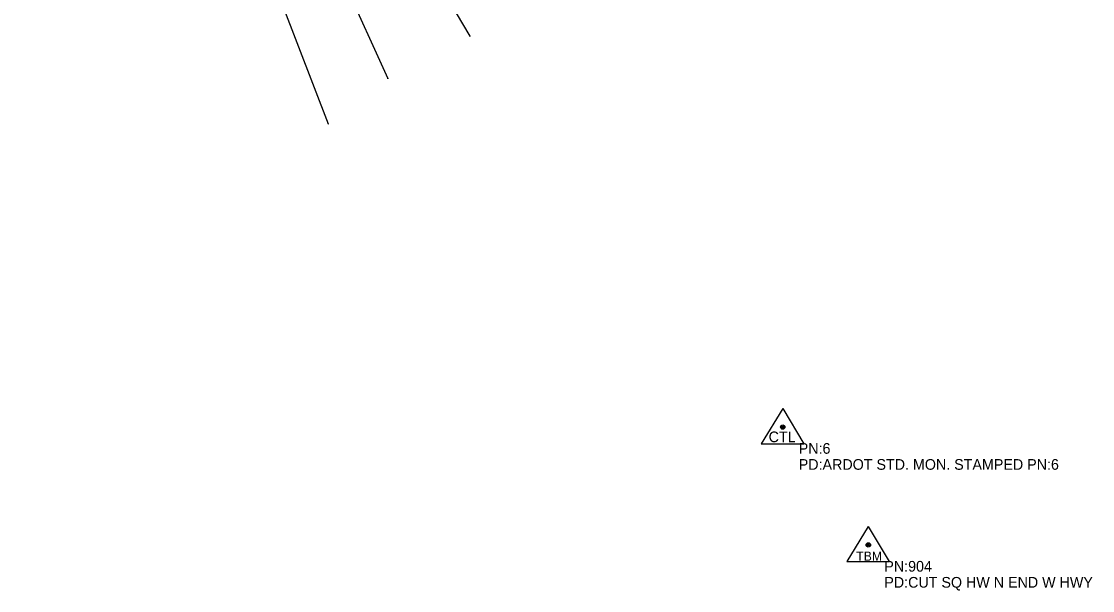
# Model space of a CAD drawing. Extents: x -99999 to 591807, y -99999 to 347168.
# Drawn here: x 589052 to 589554, y 343401 to 343667 of the extents above; entities that cross this region are included whole.
import ezdxf

# ---------------------------------------------------------------- set-up
doc = ezdxf.new("R2010")
doc.units = 0
for name, color, linetype in [('S_BREAKLINE', 7, 'Continuous'), ('S_GRD_PT_SYM', 7, 'Continuous'), ('S_PRIMARY_CTL', 7, 'Continuous'), ('S_PRIMARY_CTL_ANNOT', 7, 'Continuous')]:
    doc.layers.add(name, color=color, linetype=linetype)

msp = doc.modelspace()

# ---------------------------------------------------------------- linework, layer by layer
at = {"layer": 'S_BREAKLINE'}
for points in [[(589122.45, 343935.59), (589160.09, 343872.72), (589193.87, 343801.51), (589218.18, 343753.31), (589237.08, 343702.89), (589262.29, 343660.54)], [(589089.66, 343924.69), (589132.38, 343857.64), (589158.55, 343788.24), (589184.84, 343739), (589203.3, 343685.76), (589223.79, 343640.59)], [(589052.22, 343921.64), (589101.97, 343846.15), (589127.03, 343776.07), (589154.37, 343721.96), (589174.68, 343674.57), (589195.94, 343619.47)]]:
    msp.add_lwpolyline(points, dxfattribs=at)
at = {"layer": 'S_GRD_PT_SYM'}
for points in [[(589262.29, 343660.54), (589262.33, 343660.57), (589262.29, 343660.54), (589262.26, 343660.58), (589262.29, 343660.54), (589262.24, 343660.52), (589262.29, 343660.54), (589262.31, 343660.5)], [(589223.79, 343640.59), (589223.83, 343640.61), (589223.79, 343640.59), (589223.76, 343640.64), (589223.79, 343640.59), (589223.74, 343640.57), (589223.79, 343640.59), (589223.81, 343640.55)], [(589195.94, 343619.47), (589195.99, 343619.49), (589195.94, 343619.47), (589195.92, 343619.52), (589195.94, 343619.47), (589195.9, 343619.46), (589195.94, 343619.47), (589195.96, 343619.43)]]:
    msp.add_lwpolyline(points, close=True, dxfattribs=at)
at = {"layer": 'S_PRIMARY_CTL'}
for p, q in [((589408.75, 343486.04), (589398.71, 343469.53)), ((589408.75, 343486.04), (589418.57, 343469.53)), ((589398.71, 343469.53), (589418.57, 343469.53)), ((589448.83, 343430.82), (589438.79, 343414.3)), ((589448.83, 343430.82), (589458.65, 343414.3)), ((589438.79, 343414.3), (589458.65, 343414.3))]:
    msp.add_line(p, q, dxfattribs=at)
for centre, radius in [((589408.75, 343477.34), 1.04), ((589408.75, 343477.34), 0.609), ((589408.75, 343477.34), 0.344), ((589448.83, 343422.12), 1.04), ((589448.83, 343422.12), 0.609), ((589448.83, 343422.12), 0.344)]:
    msp.add_circle(centre, radius, dxfattribs=at)

# ---------------------------------------------------------------- texts
for s, height, p in [('CTL', 5, (589402.16, 343470.27)), ('TBM', 4.287, (589443.17, 343414.73))]:
    msp.add_text(s, height=height, rotation=360, dxfattribs=at).set_placement(p)
at = {"layer": 'S_PRIMARY_CTL_ANNOT'}
for s, p in [('PN:6', (589416.25, 343464.84)), ('PD:ARDOT STD. MON. STAMPED PN:6', (589416.25, 343457.34)), ('PN:904', (589456.33, 343409.62)), ('PD:CUT SQ HW N END W HWY', (589456.33, 343402.12))]:
    msp.add_text(s, height=5, dxfattribs=at).set_placement(p)

doc.saveas('drawing.dxf')
